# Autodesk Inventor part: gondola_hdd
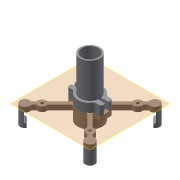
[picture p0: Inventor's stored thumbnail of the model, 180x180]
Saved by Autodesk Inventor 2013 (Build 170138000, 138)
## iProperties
Created: 2013-11
Part Number: gondola_hdd
Material: Generic
Document SubType Name: Modeling
Designer: Jonas
Density: 1 g/cm^3
Author: Jonas
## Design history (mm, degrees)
sketch "Sketch1"
  geometry: C1 r 12.5 at (0, 0); 1 further point
  constraints: 1 centre point, 1 coincident
  dimensions: "d0" = 25 diameter of C1
extrude "Extrusion1" new body sketch "Sketch1" distance "d1" = 50; taper "d2" = 0 deg; dims "d3" = 10, "d4" = 0
sketch "Sketch2"
  geometry: L1 (-17.5, 6)-(17.5, 6); L2 (17.5, 6)-(17.5, -6); L3 (17.5, -6)-(-17.5, -6); L4 (-17.5, -6)-(-17.5, 6); L5 (-17.5, 6)-(17.5, -6); L6 (17.5, 6)-(-17.5, -6); 1 further point
  constraints: 12 end point, 2 midpoint, 2 parallel, 1 horizontal, 1 perpendicular
  dimensions: "d5" = 35 distance of L2.end L3.end; "d6" = 12 distance of L1.end L2.end
extrude "Extrusion2" join sketch "Sketch2" distance "d7" = 14; taper "d8" = 0 deg
sketch "Sketch3" dims "d15" = 70, "d58" = 3.1
  geometry: L1 (0, 0)-(33.588, 33.588); L2 (0, 0)-(47.5, 0); C1 r 4.5 at (24.749, 24.749); C2 r 5 at (33.588, 33.588); 2 further points
  constraints: 4 end point, 3 coincident, 2 centre point, 1 equal length, 1 horizontal, 1 point on line, 3 other
  dimensions: "d9" = 47.5 distance of L1.start L1.end; "d10" = 45 deg angle of L2 L1; "d11" = 9 diameter of C1; "d14" = 10 diameter of C2
extrude "Extrusion3" join sketch "Sketch3" distance "d12" = 5; taper "d13" = 0 deg
sketch "Sketch4"
  geometry: L1 (28.933, 31.761)-(7.311, 10.139); L2 (31.761, 28.933)-(10.139, 7.311); L3 (33.588, 33.588)-(0, 0); C1 r 4.5 at (24.749, 24.749) reference; A1 r 5 centre (33.588, 33.588) between (28.933, 31.761) and (31.761, 28.933) reference; A2 r 12.5 centre (0, 0) between (7.311, 10.139) and (10.139, 7.311) reference; A3 r 5 centre (33.588, 33.588) between (28.933, 31.761) and (31.761, 28.933); A4 r 12.5 centre (0, 0) between (10.139, 7.311) and (7.311, 10.139); 1 further point
  constraints: 8 point on circle, 6 end point, 2 centre point, 2 coincident, 1 parallel, 1 other
  dimensions: "d16" = 4 distance between parallel lines of L2 L1
extrude "Extrusion4" join sketch "Sketch4" stored distance "d17" = 5; taper "d18" = 0 deg
sketch "Sketch5"
  geometry: A1 r 4.5 centre (-24.749, 24.749) between (-20.484, 23.313) and (-26.185, 29.013) reference; 1 further point
  constraints: 1 coincident
hole "Hole1" sketch "Sketch5" at (-24.749, 24.749) diameter "d19" = 3; stored, may be unused: countersink angle "d23" = 90 deg, drill point angle "d25" = 118 deg; dims "d20" = 6, "d21" = 5.8, "d22" = 3.05, "d24" = 8
sketch "Sketch6" dims "d26" = 93
  geometry: A1 r 5 centre (-33.588, 33.588) between (-28.933, 31.761) and (-31.761, 28.933) reference; A2 r 12.5 centre (0, 0) between (-7.311, 10.139) and (-10.139, 7.311) reference; A3 r 46.5 centre (0, 0) between (-29.279, 36.125) and (-36.125, 29.279); A4 r 5 centre (-33.588, 33.588) between (-29.279, 36.125) and (-36.125, 29.279); 1 further point
  constraints: 5 point on circle, 3 coincident, 2 centre point, 3 other
extrude "Extrusion5" join sketch "Sketch6" distance "d27" = 14; taper "d28" = 0 deg
sketch "Sketch15"
  geometry: L1 (12.5, 0)-(48.5, 0); L2 (48.5, 0)-(48.5, -9.45); L3 (48.5, -9.45)-(12.5, -9.45); L4 (12.5, -9.45)-(12.5, 0); L5 (0, -11.34)-(0, 1.89) reference; 1 further point
  constraints: 8 end point, 2 parallel, 1 horizontal, 1 horizontal alignment, 1 perpendicular
  dimensions: "d74" = 9.45 distance of L1.end L2.end; "d75" = 12.5 distance from line of point (0, 0) L4; "d87" = 48.5 distance between parallel lines of L5 L2
revolve "Revolution2" sketch "Sketch15" stored, may be unused: angle "d77" = 90 deg
chamfer "Chamfer2" distance "d78" = 1.4; stored, may be unused: second distance "d79" = 2, angle "d80" = 45 deg
fillet "Fillet2" dims "d65" = 2
sketch "Sketch16"
  geometry: L1 (-35.661, 34.036)-(-33.339, 34.964); L2 (0, 0)-(-34.5, 34.5); A1 r 1.25 centre (-34.5, 34.5) between (-35.661, 34.036) and (-33.339, 34.964); A2 r 46.5 centre (0, 0) between (-29.279, 36.125) and (-36.125, 29.279) reference; A3 r 5 centre (-33.588, 33.588) between (-29.279, 36.125) and (-36.125, 29.279) reference
  constraints: 4 end point, 2 point on circle, 1 centre point, 1 midpoint, 1 point on line
  dimensions: "d81" = 2.5 diameter of A1
revolve "Revolution3" sketch "Sketch16" stored, may be unused: angle "d82" = 90 deg
fillet "Fillet5" dims "d83" = 1
sketch "Sketch14"
  geometry: C1 r 32.5 at (0, 0); C2 r 36.5 at (0, 0); 1 further point
  constraints: 2 centre point, 2 coincident
  dimensions: "d68" = 4 radial gap between concentric circles of C2 C1; "d69" = 65 diameter of C1
extrude "Extrusion12" join sketch "Sketch14" stored distance "d70" = 7; taper "d71" = 0 deg
pattern_circular "Circular Pattern1" dims angle "d45" = 360 deg
fillet "Fillet3" dims "d66" = 2
fillet "Fillet4" dims "d72" = 2
sketch "Sketch10"
  geometry: C1 r 12.5 at (0, 0) reference; C2 r 8.5 at (0, 0); C3 r 10.1 at (0, 0); C4 r 12.5 at (0, 0)
  constraints: 3 centre point, 3 coincident, 1 concentric
  dimensions: "d47" = 17 diameter of C2; "d48" = 20.2 diameter of C3
extrude "Extrusion8" cut sketch "Sketch10" stored distance "d49" = 5.37; taper "d50" = 0 deg
sketch "Sketch11"
  geometry: C1 r 10.1 at (0, 0) reference; C2 r 8.5 at (0, 0)
  constraints: 1 centre point, 1 coincident
  dimensions: "d51" = 17 diameter of C2
extrude "Extrusion9" cut sketch "Sketch11" stored distance "d52" = 5.37; taper "d53" = 0 deg
sketch "Sketch12"
  geometry: L1 (0, 0)-(0, 12) reference; L2 (14, 10)-(14, 2) reference; L3 (14, 7.55)-(14, 4.45); L4 (14, 4.45)-(10.168, 4.45); L5 (10.168, 4.45)-(8.5, 3.05); L6 (8.5, 3.05)-(5, 3.05); L7 (5, 3.05)-(5, 8.95); L8 (5, 8.95)-(8.5, 8.95); L9 (8.5, 8.95)-(10.168, 7.55); L10 (10.168, 7.55)-(14, 7.55); L11 (5, 28.54)-(5, 30.199) reference; 8 further points
  constraints: 16 end point, 5 midpoint, 3 parallel, 3 vertical alignment, 2 perpendicular, 2 point on line, 1 coincident, 1 horizontal alignment
  dimensions: "d54" = 5.9 distance of L6.end L7.end; "d57" = 3.5 distance of L7.end L8.end; "d58" = 3.1 distance between parallel lines of L4 L10; "d59" = 50 deg angle of L7 L9
extrude "Extrusion10" cut sketch "Sketch12" stored distance "d60" = 5.37; taper "d61" = 0 deg
sketch "Sketch13"
  geometry: L1 (0, 5.9)-(7.84, 5.9) reference; L2 (1.774, 5.9)-(7.84, 5.9); L3 (1.839, -0.324)-(7.945, -0.324); A1 r 10.1 centre (17.5, 2.95) between (7.84, 5.9) and (7.84, 0) reference; A2 r 10.1 centre (17.5, 2.95) between (7.84, 5.9) and (7.945, -0.324); A3 r 16 centre (17.5, 2.95) between (1.774, 5.9) and (1.839, -0.324)
  constraints: 4 end point, 4 point on circle, 3 coincident, 2 centre point, 1 collinear, 1 concentric, 1 parallel, 1 point on line
  dimensions: "d62" = 5.9 radial gap between concentric circles of A1 A3
extrude "Extrusion11" cut sketch "Sketch13" distance "d63" = 7; taper "d64" = 0 deg
mirror "Mirror1"
workplane "Work Plane2"
sketch "Sketch17"
  geometry: 1 further point
split "Split2"
  body "Solid1"
node "Projected Loop1"
node "Projected Loop2"
body "Solid4"
body "Solid5"
